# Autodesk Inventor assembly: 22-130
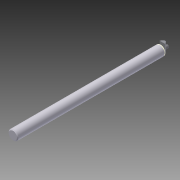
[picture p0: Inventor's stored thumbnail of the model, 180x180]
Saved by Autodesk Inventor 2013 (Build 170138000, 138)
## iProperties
Created: 2004-11
Part Number: 22-130
Document SubType Name: Assembly
Designer: Autodesk, Inc.
Manufacturer: Standard
Standards Organization: Custom
Description: BIN MOUNTING SLIDE RAIL
Vendor: PARKER IPS
Catalog Web Link: http://www.parker.com/ead/cm1.asp?cmid=809
Mass: 535.841 g
Surface Area: 338.388 cm^2
Volume: 195.641 cm^3
Density: 2.7389 g/cm^3
CAGE: 1LJX3
Dept. ID: Product Design
Description #2: ---
Finish #1: ---
Finish #2: ---
Material ID: ---
Project Number: ---
Author: Autodesk, Inc.
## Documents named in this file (5)
- Z:\_DATEN\Test Station\Components\22-130.iam
- Z:\_DATEN\Test Station\Components\22-130.ipt
- Z:\_DATEN\Test Station\Components\20-058.ipt
- Z:\_DATEN\Test Station\Components\Nylon Washer.ipt
- C:\Users\kelleyb.ADS\Desktop\Samples MIGRATED 2009 224 RTM_1\Standard Parts\Test Station Content\Fastners\20-XXX TSlot Nuts.ipt
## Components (3 placed, 3 different names)
1. 22-130:1 — Mate:1, Flush:1
2. 20-058:1 — Mate:1, Mate:2
3. Nylon Washer:1 — Flush:1, Mate:2
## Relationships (3: Mate 2, Flush 1)
- Mate:1: 22-130:1 ↔ 20-058:1
- Flush:1: 22-130:1 ↔ Nylon Washer:1
- Mate:2: 20-058:1 ↔ Nylon Washer:1
